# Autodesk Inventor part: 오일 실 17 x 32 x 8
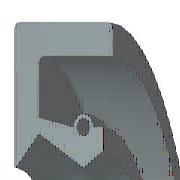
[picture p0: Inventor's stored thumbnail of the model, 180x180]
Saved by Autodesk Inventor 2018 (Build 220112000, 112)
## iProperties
Created: 2012-02
Part Number: 오일 실 17 x 32 x 8
Material: 고무
Description: 샤프트 실 링
Document SubType Name: Modeling
Standard: JIS B 2402
Designer: mdu-01
Standards Organization: JIS
Language: ko-KR
Size Designation: D 17 x 32 x 8
Categories: <MemberInstance><Categories><Category DisplayName="샤프트 부품" InternalName="7f7aeb1f-a693-4053-b835-cee3144e0d98" Mnemonic="SHFT"><Category DisplayName="실링" Intern
Density: 0.93 g/cm^3
Appearance: 고무 - 검은색 - 버전 1.1
IsCustomPart: 1
Author: mdu-01
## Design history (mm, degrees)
revolve "본체" stored, may be unused: angle "d17" = 90 deg
revolve "스프링1" stored, may be unused: angle "d18" = 90 deg
body "Solid1"
sketch "스케치1"
  geometry: L1 (0, 16)-(8, 16); L2 (8, 14.25)-(1.75, 14.25); L3 (1.75, 10.25)-(4.9, 8.5); L4 (4.9, 8.5)-(0, 8.5); L5 (0, 0)-(9.586, 0) reference; L6 (4.9, 8.5)-(6.3, 9.375); L7 (0, 18)-(0, -3) reference; L8 (-1.941, 0)-(11.507, 0) reference; L9 (4.2, 10.6)-(1.75, 11.21); L10 (1.75, 11.21)-(1.75, 14.25); L11 (0, 16)-(0, 8.588); L12 (4.9, 8.5)-(0, 8.5); L13 (1.75, 10.25)-(0.152, 8.528); L14 (8, 16)-(8, 14.25); L15 (5.6, 10.6)-(6.3, 10.6); L16 (6.3, 10.6)-(6.3, 9.375); C1 r 0.455 at (4.9, 10.6); A1 r 0.7 centre (4.9, 10.6) between (5.6, 10.6) and (4.2, 10.6); A2 r 0.088 centre (0.088, 8.588) between (0, 8.588) and (0.152, 8.528); 1 further point
  constraints: 28 end point, 5 horizontal alignment, 5 point on line, 4 point on circle, 4 vertical alignment, 3 centre point, 3 tangent, 2 collinear, 2 horizontal, 2 perpendicular, 1 coincident, 1 parallel
  dimensions: "d0" = 32 diameter of L1 L5 (= SD2); "d1" = 1.75 distance of L1.end L2.start (= SD); "d2" = 0.91 diameter of C1 (= SPDI); "d3" = 1.4 diameter of A1 (= SPDA); "d4" = 17 diameter of L3.end L5 (= NND); "d5" = 20.5 diameter of L3.start L5 (= TKDM); "d7" = 22.42 diameter of L9.end L5 (= TKDM + 0.24 x SWDT); "d8" = 1.75 distance between parallel lines of L11 L10 (= SD); "d9" = 4.9 distance from line of L11 C1.centre (= SPDST); "d10" = 21.2 diameter of C1.centre L5 (= HLDM); "d11" = 0.0875 radius of A2 (= 0.25 x LAB); "d12" = 6.3 distance between parallel lines of L11 L16 (= SDI); "d13" = 18.75 diameter of L6.end L5 (= ABDM); "d14" = 8 distance from line of L11 L1.end (= SWDT)
fillet "모깎기1" dims "d6" = 0.3 (= RR)
other parameters: "SD2" = 32 [user parameter; used in 1 equation term], "SWDT" = 8 [user parameter; used in 2 equation terms], "RR" = 0.3 [user parameter; used in 1 equation term], "SD" = 1.75 [user parameter; used in 2 equation terms], "NND" = 17 [user parameter; used in 1 equation term], "SPDA" = 1.4 [user parameter; used in 1 equation term], "SPDI" = 0.91 [user parameter; used in 1 equation term], "TKDM" = 20.5 [user parameter; used in 2 equation terms], "HLDM" = 21.2 [user parameter; used in 1 equation term], "ABDM" = 18.75 [user parameter; used in 1 equation term], "SDI" = 6.3 [user parameter; used in 1 equation term], "SPDST" = 4.9 [user parameter; used in 1 equation term], "LAB" = 0.35 [user parameter; used in 1 equation term], "d15" = 0, "d16" = 0, "d19" = 0
